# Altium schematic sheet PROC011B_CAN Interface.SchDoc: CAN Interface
size 431 x 279 mm; Date: Not shown in title block; ApprovedBy: Not shown in title block; CheckedBy: Not shown in title block; Author: Not shown in title block; CompanyName: Not shown in title block; Engineer: Not shown in title block; Organization: Not shown in title block; Address1: Not shown in title block; Address2: Not shown in title block; Address3: Not shown in title block; Address4: Not shown in title block; DocumentNumber: 1; Revision: Use project parameter SCH_Rev; SheetNumber: 14; SheetTotal: 17; PageSetup: Record=PageOptions¦CenterHorizontal=True¦CenterVertical=True¦PrintScale=1.00¦XCorrection=1.00¦YCorrection=1.00¦PrintKind=0¦BorderSize=5000000¦LeftOffset=0¦BottomOffset=0¦Orientation=2¦PaperLength=1000¦PaperWidth=1000¦Scale=100¦PaperSource=15¦PrintQuality=600¦MediaType=1¦DitherType=10¦PaperKind=Letter¦PrintScaleMode=1
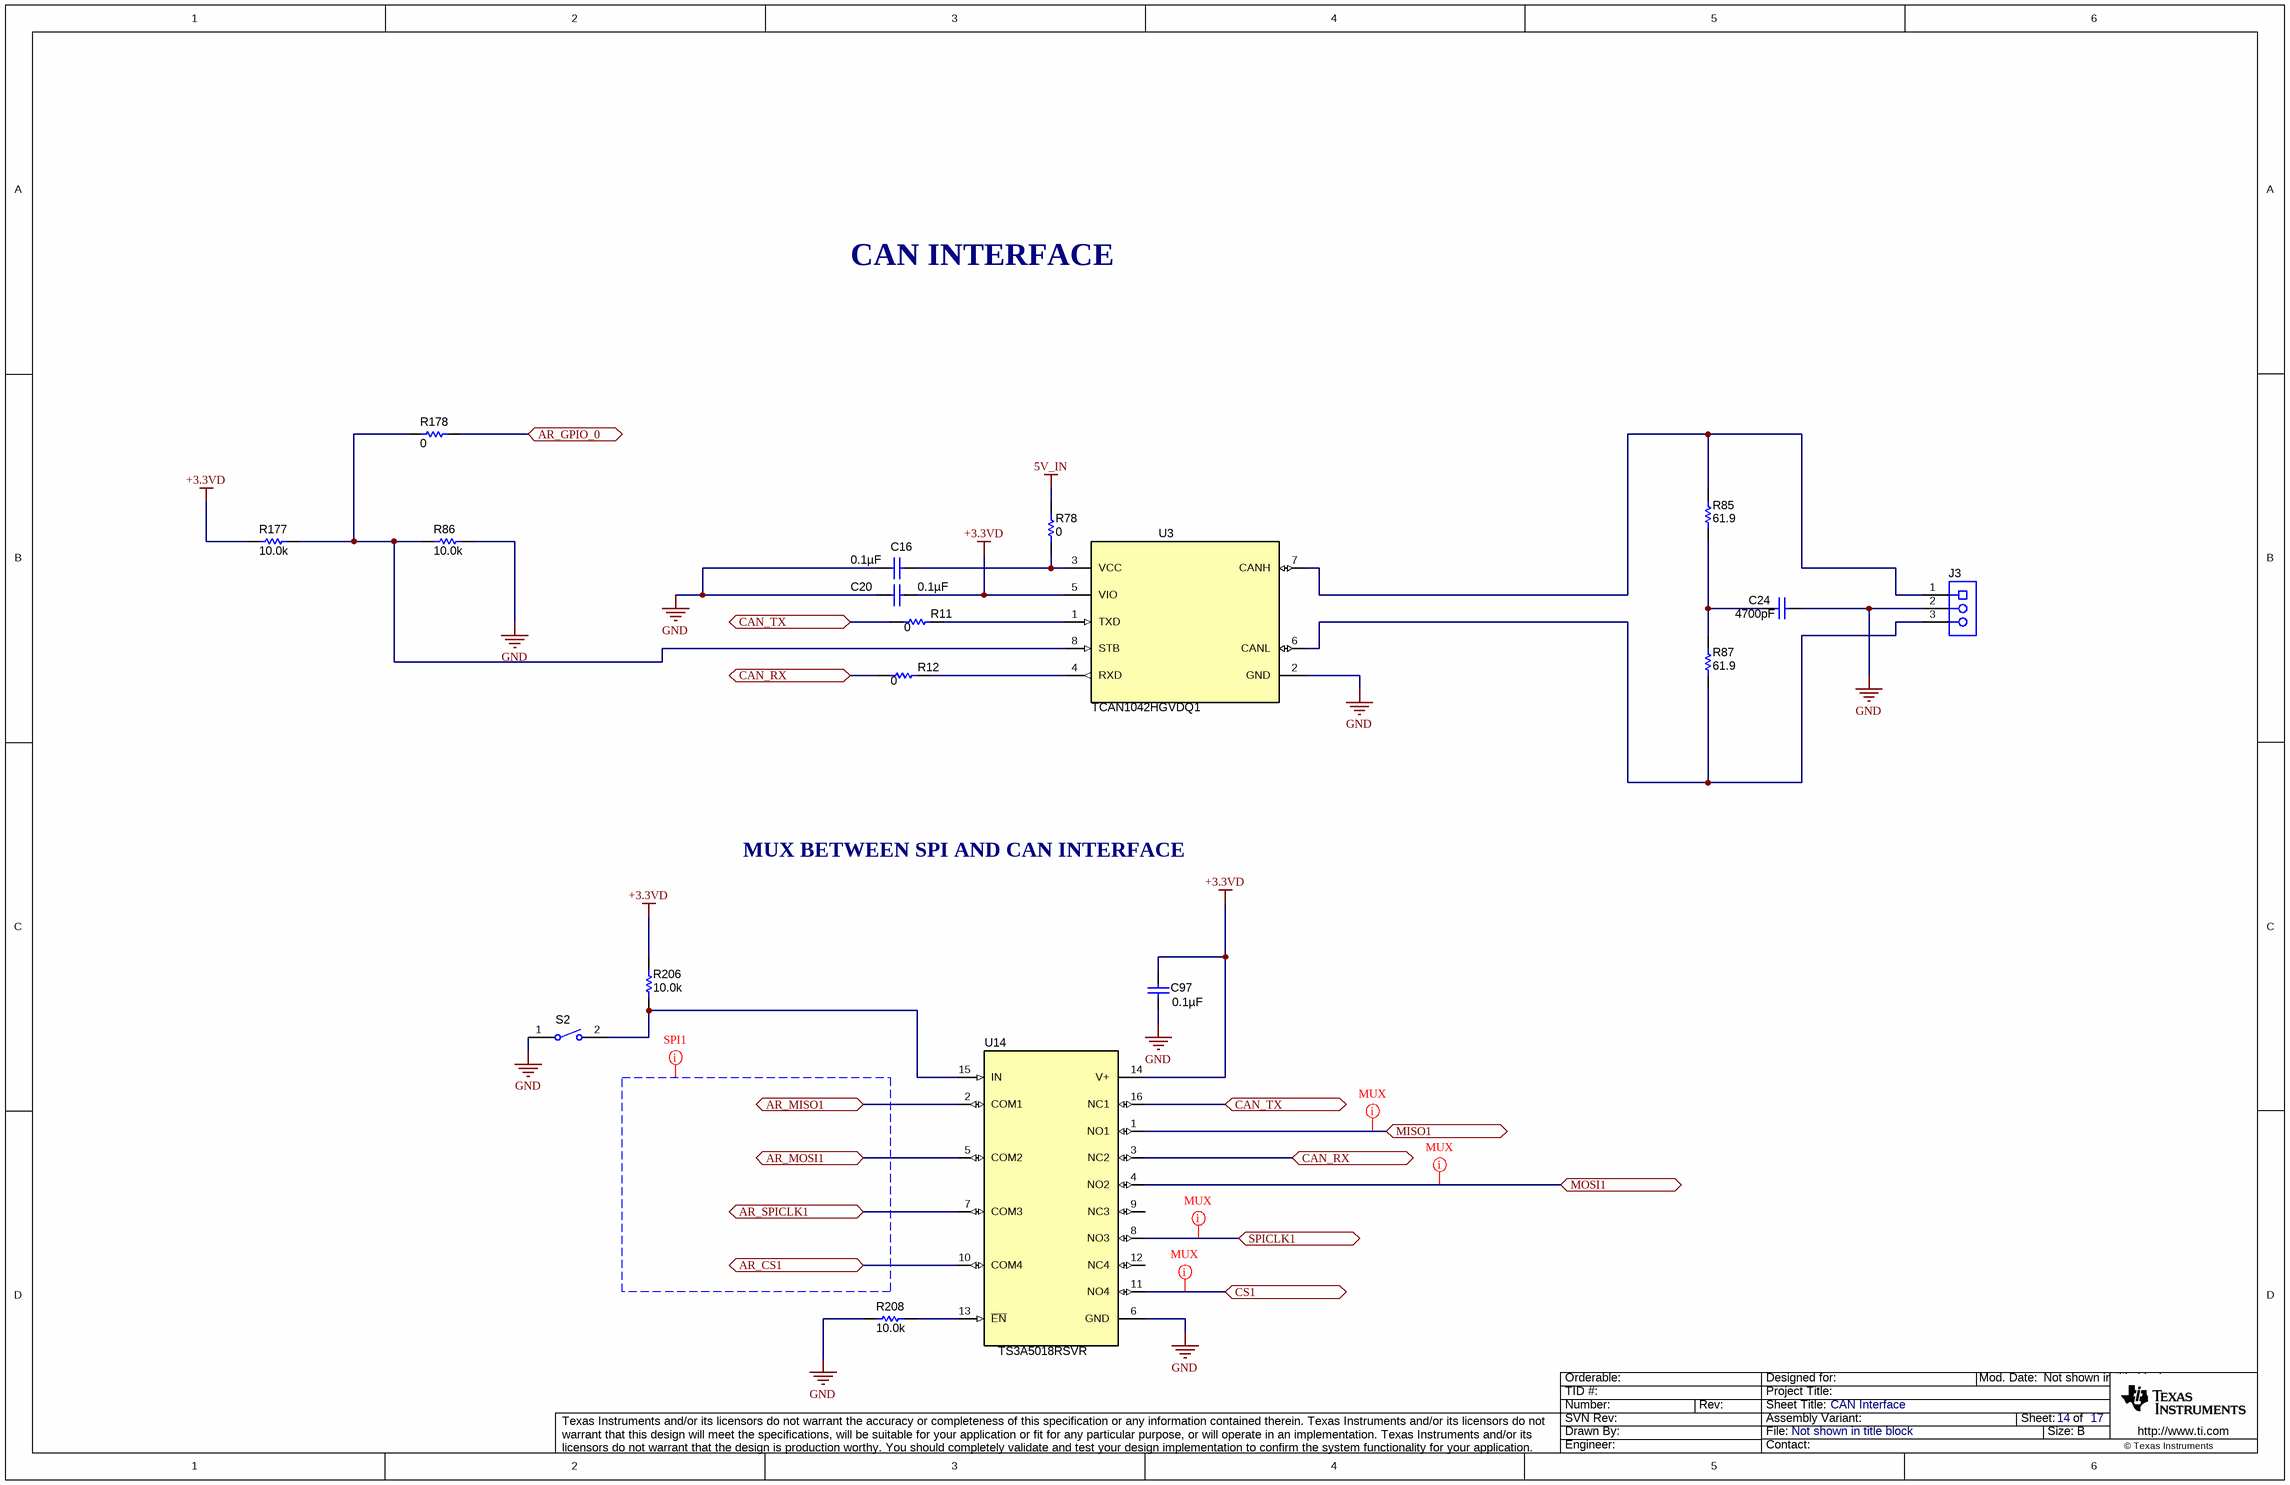
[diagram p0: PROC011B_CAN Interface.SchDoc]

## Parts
C16  ValueDisplayed: 0.1µF  [0402L]  (hidden comment: C0402C104K8RACTU)
C20  ValueDisplayed: 0.1µF  [0402L]  (hidden comment: C0402C104K8RACTU)
C24  ValueDisplayed: 4700pF  [0402L]  (hidden comment: C1005X7R1H472K050BA)
C97  ValueDisplayed: 0.1µF  [0402L]  (hidden comment: C0402C104K8RACTU)
J3  OSTTE030161  [On-Shore_OSTTE030161]  (value not drawn)
R11  ValueDisplayed: 0  [0402L]  (hidden comment: ERJ-2GE0R00X)
R12  ValueDisplayed: 0  [0402L]  (hidden comment: ERJ-2GE0R00X)
R78  ValueDisplayed: 0  [0402L]  (hidden comment: ERJ-2GE0R00X)
R85  ValueDisplayed: 61.9  [0402L]  (hidden comment: CRCW040261R9FKED)
R86  ValueDisplayed: 10.0k  [0402L]  (hidden comment: CRCW040210K0FKED)
R87  ValueDisplayed: 61.9  [0402L]  (hidden comment: CRCW040261R9FKED)
R177  ValueDisplayed: 10.0k  [0402L]  (hidden comment: CRCW040210K0FKED)
R178  ValueDisplayed: 0  [0402L]  (hidden comment: ERJ-2GE0R00X)
R206  ValueDisplayed: 10.0k  [0402L]  (hidden comment: CRCW040210K0FKED)
R208  ValueDisplayed: 10.0k  [0402L]  (hidden comment: CRCW040210K0FKED)
S2  CHS-01TB  [SW_CHS-01TB]  (value not drawn)
U3  TCAN1042HGVDQ1  [D0008A_L]
U14  TS3A5018RSVR  [RSV0016A]

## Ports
AR_CS1, AR_GPIO_0, AR_MISO1, AR_MOSI1, AR_SPICLK1, CAN_RX, CAN_TX, CS1, MISO1, MOSI1, SPICLK1

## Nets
5V_IN: R78.2
+3.3VD: C20.2 C97.2 R177.1 R206.2 U3.5(VIO) U14.14(V+)
GND: C16.1 C20.1 C24.1 C97.1 J3.2 R86.2 R208.2 S2.1 U3.2(GND) U14.6(GND)
AR_CS1: U14.10(COM4) ; port AR_CS1
AR_GPIO_0: R178.2 ; port AR_GPIO_0
AR_MISO1: U14.2(COM1) ; port AR_MISO1
AR_MOSI1: U14.5(COM2) ; port AR_MOSI1
AR_SPICLK1: U14.7(COM3) ; port AR_SPICLK1
CAN_RX: R12.1 U14.3(NC2) ; port CAN_RX
CAN_TX: R11.1 U14.16(NC1) ; port CAN_TX
CS1: U14.11(NO4) ; port CS1
MISO1: U14.1(NO1) ; port MISO1
MOSI1: U14.4(NO2) ; port MOSI1
SPICLK1: U14.8(NO3) ; port SPICLK1
NetC16_2: C16.2 R78.1 U3.3(VCC)
NetC24_2: C24.2 R85.1 R87.2
NetJ3_1: J3.1 R85.2 U3.7(CANH)
NetJ3_3: J3.3 R87.1 U3.6(CANL)
NetR11_2: R11.2 U3.1(TXD)
NetR12_2: R12.2 U3.4(RXD)
NetR86_1: R86.1 R177.2 R178.1 U3.8(STB)
NetR206_1: R206.1 S2.2 U14.15(IN)
NetR208_1: R208.1 U14.13(~{EN})

Not connected (* = marked no-connect by the designer): U14 9(NC3) 12(NC4)

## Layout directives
net class MUX_TO_J1: CS1, MISO1, MOSI1, SPICLK1
net class SPI1: (no net found under the mark)

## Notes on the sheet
- CAN INTERFACE
- MUX BETWEEN SPI AND CAN INTERFACE

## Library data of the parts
C16 C20 C97 = CMP-0078241-1: CAP, CERM, 0.1 µF, 10 V,+/- 10%, X7R, 0402; Manufacturer: Kemet; TaMin_C: -55°C; Polarized: N; SizeAreaWB_mm2: 3; U/M: EA; Value: 0.1uF; TaMax_C: 125°C; SizeZ_mm: 0.6; SizeX_mm: 1; SizeY_mm: 0.5; Cap_Case: 0402; Value2: 10V; Cap_F: 100nF; AEC Category: Q200
C24 = CMP-0078221-1: CAP, CERM, 4700 pF, 50 V,+/- 10%, X7R, 0402; Manufacturer: TDK; TaMin_C: -55°C; Polarized: N; SizeAreaWB_mm2: 3; U/M: EA; Value: 4700pF; TaMax_C: 125°C; SizeZ_mm: 0.6; SizeX_mm: 1; SizeY_mm: 0.5; Cap_Case: 0402; Value2: 50V; Cap_F: 4.7nF; AEC Category: Q200
J3 = CMP-0075352-1: Terminal Block, 3.5mm, 3x1, Tin, R/A, TH; Manufacturer: On-Shore Technology; CNHeader: False; Current_A: 10A; Green_Lifecycle: Not Set; Gender: Female; Cert_CSA: Y; Green_REACh: Incomplete; Voltage_V: 125V; Row_Count: 1; Pitch_mm: 3.5; CT: True
R11 R12 R178 = CMP-0026992-2: RES, 0, 5%, 0.063 W, 0402; Manufacturer: Panasonic; Power_W: 63mW; TempCo: 600 ppm/C; Value_Code: 0000; U/M: EA; Value: 0; EIA_Code: E24; SizeX_mm: 1; SizeY_mm: 0.5; SizeZ_mm: 0.6; Value2: 0.063W; CompType: Resistor; VDC_V: 50V; AEC Category: Q200; INSTALATION: DNP
R78 = CMP-0026992-2: RES, 0, 5%, 0.063 W, 0402; Manufacturer: Panasonic; Power_W: 63mW; TempCo: 600 ppm/C; Value_Code: 0000; U/M: EA; Value: 0; EIA_Code: E24; SizeX_mm: 1; SizeY_mm: 0.5; SizeZ_mm: 0.6; Value2: 0.063W; VDC_V: 50V; AEC Category: Q200
R85 R87 = CMP-0026491-1: RES, 61.9, 1%, 0.063 W, 0402; Manufacturer: Vishay-Dale; Power_W: 63mW; TempCo: 100 ppm/C; Value_Code: 61R9; U/M: EA; Value: 61.9; EIA_Code: E96; SizeX_mm: 1; SizeY_mm: 0.5; SizeZ_mm: 0.6; Value2: 0.063W; VDC_V: 50V; AEC Category: Q200
R86 = CMP-0025958-2: RES, 10.0 k, 1%, 0.063 W, 0402; Manufacturer: Vishay-Dale; Power_W: 63mW; TempCo: 100 ppm/C; Value_Code: 10k0; U/M: EA; Value: 10.0k; EIA_Code: E96; Res_ohm: 10k; SizeX_mm: 1; SizeY_mm: 0.5; SizeZ_mm: 0.6; Value2: 0.063W; VDC_V: 50V; AEC Category: Q200
R177 = CMP-0025958-2: RES, 10.0 k, 1%, 0.063 W, 0402; Manufacturer: Vishay-Dale; Power_W: 63mW; TempCo: 100 ppm/C; Value_Code: 10k0; U/M: EA; Value: 10.0k; EIA_Code: E96; Res_ohm: 10k; SizeX_mm: 1; SizeY_mm: 0.5; SizeZ_mm: 0.6; Value2: 0.063W; CompType: Resistor; VDC_V: 50V; AEC Category: Q200; INSTALATION: DNP
R206 R208 = CMP-0025958-2: RES, 10.0 k, 1%, 0.063 W, 0402; Manufacturer: Vishay-Dale; Power_W: 63mW; TempCo: 100 ppm/C; Value_Code: 10k0; U/M: EA; Value: 10.0k; EIA_Code: E96; Res_ohm: 10k; SizeX_mm: 1; SizeY_mm: 0.5; SizeZ_mm: 0.6; Value2: 0.063W; CompType: Resistor; VDC_V: 50V; AEC Category: Q200
S2 = CMP-0002163-2: Switch, Slide, SPST, Top Slide, SMT; Manufacturer: Copal Electronics; CurrentRating_mA: 100A; SwitchFunction: Off-On; VDC_V: 6V; PositionCount: 1
U3 = CMP-0075992-1: Automotive Fault Protected CAN Transceiver With Flexible Data-Rate, D0008A (SOIC-8); Manufacturer: Texas Instruments; Alternate PartNumber: TCAN1042HGVDRQ1; SizeAreaWB_mm2: 56.58; SizeArea_mm2: 30.38; SizeZ_mm: 1.75; SizeY_mm: 6.2; U/M: EA; CompType: IC; SizeX_mm: 4.9
U14 = CMP-0067415-1: 10-Ohm Quad SPDT Analog Switch, RSV0016A (UQFN-16); Alternate Manufacturer: Texas Instruments; SizeAreaWB_mm2: 10.08; U/M: EA; SizeZ_mm: 0.55; SizeX_mm: 1.8; SizeY_mm: 2.6; SizeArea_mm2: 4.68; CompType: IC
